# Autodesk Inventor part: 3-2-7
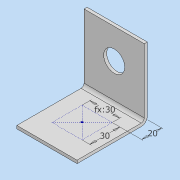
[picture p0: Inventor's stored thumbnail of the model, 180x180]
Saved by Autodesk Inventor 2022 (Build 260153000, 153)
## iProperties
Created: 2021-07
Part Number: 3-2-7
Material: 一般
Document SubType Name: Modeling
Designer: DesignLab
Density: 1 g/cm^3
Appearance: 既定
Author: DesignLab
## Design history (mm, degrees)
sketch "スケッチ1"
  geometry: L1 (0, 0)-(70, 0); L2 (70, 0)-(70, 70); L3 (70, 70)-(0, 70); L4 (0, 70)-(0, 0)
  constraints: 8 end point, 2 parallel, 1 horizontal, 1 perpendicular
  dimensions: "d0" = 70 distance of L3.end L2.end; "d1" = 70 distance of L2.end L1.end
extrude "押し出し1" new body sketch "スケッチ1" taper "d3" = 0 deg; stored distance "全幅" = 60
fillet "フィレット1" dims "d4" = 6
feature "シェル1" dims "d5" = 3
sketch "スケッチ2"
  geometry: L1 (0, -6)-(60, -6) reference; 3 further points
  constraints: 1 midpoint, 1 vertical alignment
  dimensions: "d6" = 40 distance from line of point (30, 34) L1
hole "穴1" sketch "スケッチ2" at (30, 34) diameter "d7" = 21; stored, may be unused: countersink angle "d11" = 90 deg, drill point angle "d13" = 118 deg; dims "d8" = 6, "d9" = 4, "d10" = 2, "d12" = 8
sketch "スケッチ3"
  geometry: L1 (15, -44)-(45, -44); L2 (45, -44)-(45, -14); L3 (45, -14)-(15, -14); L4 (15, -14)-(15, -44); L5 (15, -44)-(45, -14); L6 (45, -44)-(15, -14); L7 (60, 6)-(0, 6) reference; 4 further points
  constraints: 12 end point, 4 midpoint, 2 parallel, 1 horizontal, 1 perpendicular, 1 vertical alignment
  dimensions: "d14" = 30 distance of L3.end L2.end (= 0.5 x 全幅); "d15" = 30 distance of L2.end L1.end; "d16" = 20 distance between parallel lines of L3 L7
node "ソリッド1"
